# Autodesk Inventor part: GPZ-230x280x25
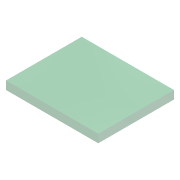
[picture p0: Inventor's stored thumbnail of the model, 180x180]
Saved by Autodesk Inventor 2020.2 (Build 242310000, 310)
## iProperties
Created: 2015-11
Part Number: GPZ-230x280x25
Material: Ogólny
Document SubType Name: Modeling
Designer: F.Stasiak
Density: 1 g/cm^3
Appearance: Przezroczysty - zielony 1
Catalog Web Link: www.expertbooks.pl
Manager: www.cadconsulting.pl
Company: Fabian Stasiak CAD Consulting
Author: F.Stasiak
Subject: Zbiór ćwiczeń. Autodesk Inventor 2020. Kurs Professional
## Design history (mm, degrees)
sketch "Szkic1"
  geometry: L1 (-140, 115)-(140, 115); L2 (140, 115)-(140, -115); L3 (140, -115)-(-140, -115); L4 (-140, -115)-(-140, 115); L5 (-140, 115)-(140, -115); L6 (140, 115)-(-140, -115); 1 further point
  constraints: 12 end point, 2 midpoint, 2 parallel, 1 horizontal, 1 perpendicular
  dimensions: "d0" = 280 distance of L2.end L3.end; "d1" = 230 distance of L1.end L2.end
extrude "Wyciągnięcie proste1" new body sketch "Szkic1" distance "d2" = 25; taper "d3" = 0 deg
node "Bryła1"
